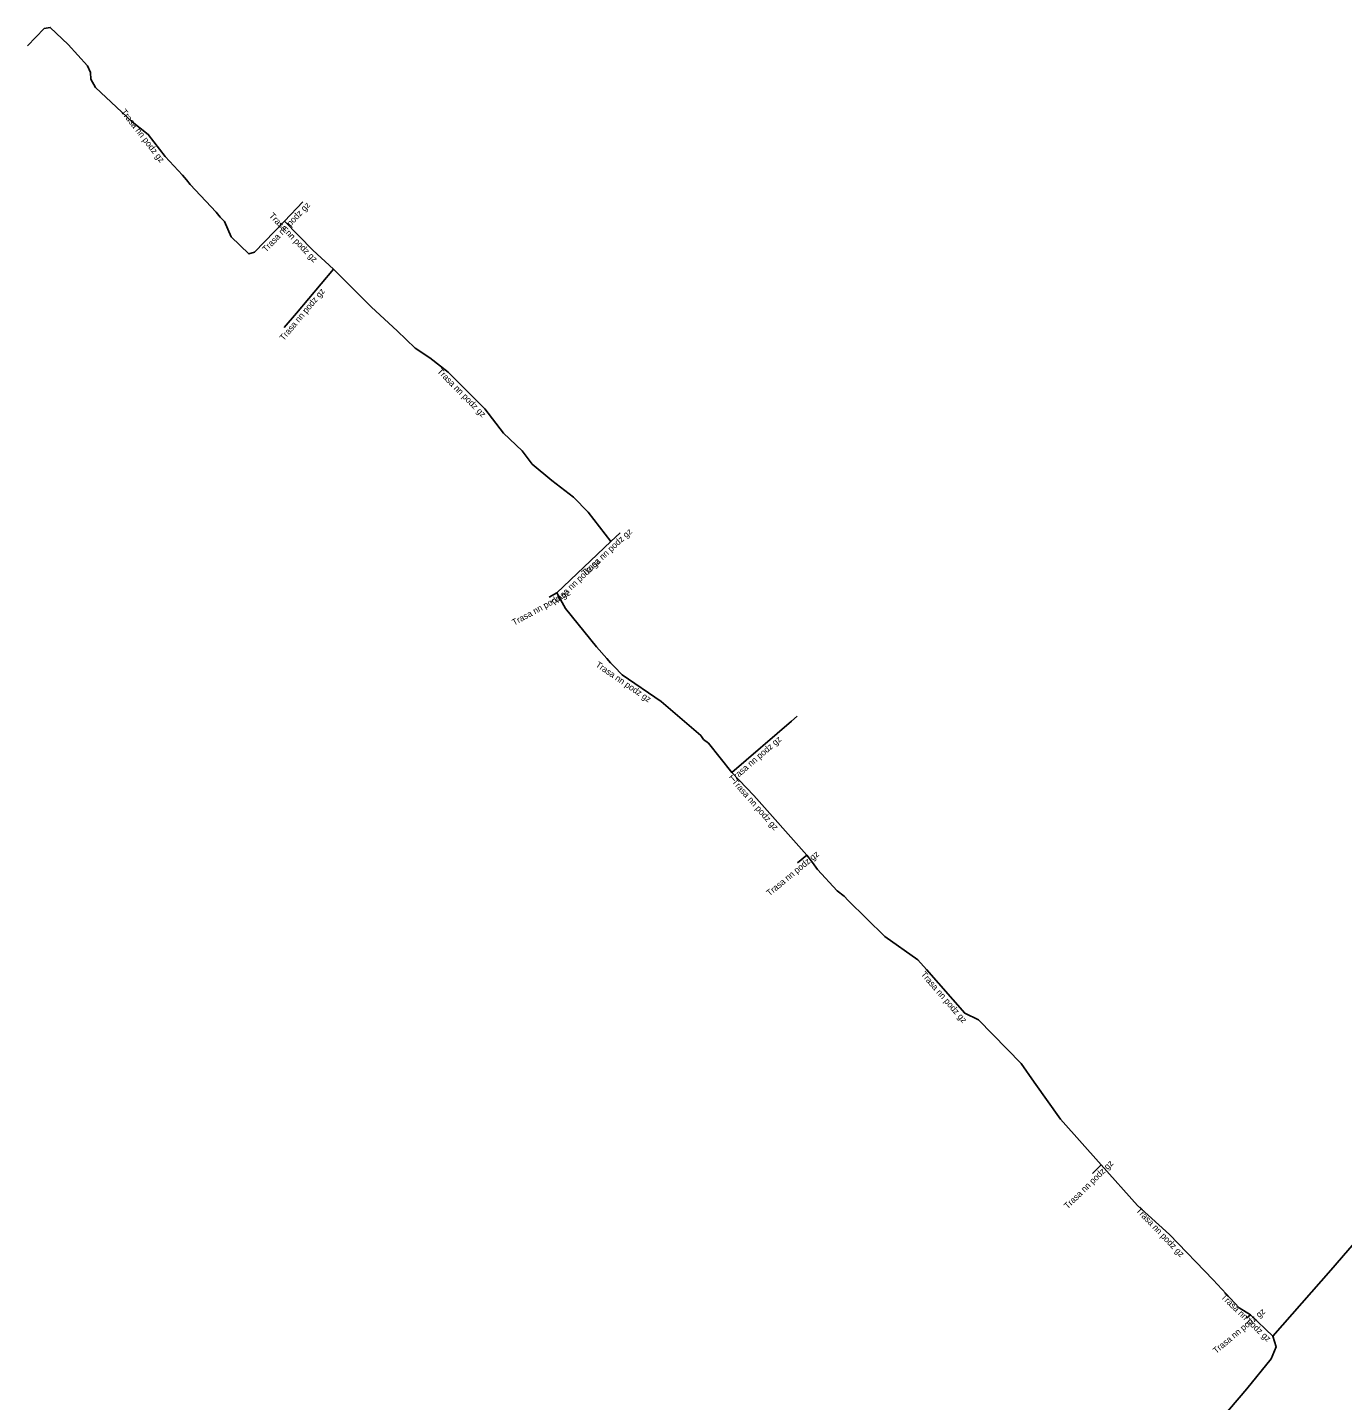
# Model space of a CAD drawing. Extents: x -747130 to -746834, y -1018555 to -1017941.
# Drawn here: x -747129.6 to -747024.9, y -1018393 to -1018283.6 of the extents above; entities that cross this region are included whole.
import ezdxf

# ---------------------------------------------------------------- set-up
doc = ezdxf.new("R2010")
doc.units = 0
doc.layers.add('Popiskový text - Ostatní atributy Trasy', color=7, linetype='Continuous')
doc.layers.add('Spojnice NN', color=7, linetype='Continuous')

msp = doc.modelspace()

# ---------------------------------------------------------------- linework, layer by layer
at = {"layer": 'Spojnice NN'}
for points in [[(-747129.62, -1018285.07), (-747128.29, -1018283.69), (-747127.81, -1018283.61), (-747126.37, -1018284.96), (-747124.84, -1018286.67), (-747124.61, -1018287.19), (-747124.57, -1018287.73), (-747124.21, -1018288.38), (-747121.28, -1018291.12), (-747120.01, -1018292.13), (-747118.65, -1018293.88), (-747117.29, -1018295.38), (-747116.96, -1018295.74), (-747116.67, -1018296.13), (-747114.61, -1018298.32), (-747114.28, -1018298.72), (-747113.95, -1018299.06), (-747113.41, -1018300.29), (-747112, -1018301.65), (-747111.54, -1018301.5), (-747109.15, -1018299.04)], [(-747109.15, -1018299.04), (-747107.7, -1018297.5)], [(-747109.15, -1018299.04), (-747106.9, -1018301.36), (-747105.27, -1018302.85)], [(-747109.2, -1018307.51), (-747108.2, -1018306.36), (-747105.27, -1018302.85)], [(-747105.27, -1018302.85), (-747102.24, -1018305.9), (-747100.19, -1018307.78), (-747098.77, -1018309.16), (-747097.6, -1018309.91), (-747096.12, -1018311.06), (-747093.22, -1018313.99), (-747091.74, -1018315.92), (-747090.23, -1018317.33), (-747089.45, -1018318.39), (-747087.87, -1018319.7), (-747086.15, -1018321.03), (-747085, -1018322.22), (-747083.18, -1018324.55)], [(-747083.18, -1018324.55), (-747082.45, -1018323.87)], [(-747087.47, -1018328.65), (-747083.18, -1018324.55)], [(-747087.47, -1018328.65), (-747088.09, -1018328.99)], [(-747087.47, -1018328.65), (-747086.8, -1018329.9), (-747084.32, -1018332.95), (-747083.5, -1018333.86), (-747083.21, -1018334.21), (-747082.91, -1018334.52), (-747082.29, -1018335.17), (-747079.18, -1018337.29), (-747076.03, -1018339.99), (-747075.8, -1018340.32), (-747075.42, -1018340.6), (-747073.54, -1018342.96)], [(-747068.36, -1018338.46), (-747068.8, -1018338.87), (-747073.54, -1018342.96)], [(-747073.54, -1018342.96), (-747071.79, -1018344.77), (-747067.59, -1018349.54)], [(-747067.59, -1018349.54), (-747068.33, -1018350.15)], [(-747067.59, -1018349.54), (-747067.12, -1018350.11), (-747066.73, -1018350.68), (-747065.16, -1018352.38), (-747064.61, -1018352.8), (-747064.28, -1018353.15), (-747061.37, -1018356), (-747058.76, -1018357.87), (-747058.05, -1018358.63), (-747055.01, -1018362.13), (-747053.92, -1018362.65), (-747050.53, -1018366.13), (-747049.5, -1018367.62), (-747047.4, -1018370.55), (-747044.15, -1018374.21)], [(-747030.49, -1018387.84), (-747025.86, -1018382.59), (-747018.77, -1018374.36), (-747011.83, -1018366.33), (-747006.47, -1018360.35), (-747002.76, -1018356.27), (-747001.95, -1018355.16), (-747001.69, -1018354.42), (-747001.81, -1018353.62)], [(-747044.15, -1018374.21), (-747044.85, -1018374.9)], [(-747032.28, -1018386.14), (-747033.18, -1018385.58), (-747035.23, -1018383.36), (-747038.72, -1018379.74), (-747041.25, -1018377.44), (-747044.15, -1018374.21)], [(-747032.28, -1018386.14), (-747032.59, -1018386.4)], [(-747030.49, -1018387.84), (-747032.28, -1018386.14)], [(-747037.93, -1018398.33), (-747032.55, -1018392.05), (-747030.63, -1018389.65), (-747030.23, -1018388.68), (-747030.49, -1018387.84)]]:
    msp.add_lwpolyline(points, dxfattribs=at)

# ---------------------------------------------------------------- texts
at = {"layer": 'Popiskový text - Ostatní atributy Trasy'}
for rotation, p in [(307.8523, (-747122.22, -1018290.35)), (46.7241, (-747110.62, -1018301.55)), (314.1225, (-747110.43, -1018298.65)), (50.1463, (-747109.22, -1018308.6)), (314.7052, (-747097.05, -1018311.04)), (42.9691, (-747085.22, -1018327.34)), (43.7027, (-747087.69, -1018329.76)), (28.7398, (-747090.88, -1018331.26)), (325.7188, (-747084.45, -1018334.48)), (40.7899, (-747073.47, -1018343.75)), (311.364, (-747073.58, -1018343.72)), (39.4996, (-747070.55, -1018352.82)), (310.9766, (-747058.55, -1018359.05)), (44.5878, (-747046.82, -1018377.75)), (313.9525, (-747041.42, -1018377.87)), (316.4772, (-747034.66, -1018384.78)), (39.9869, (-747035, -1018389.27))]:
    msp.add_text('Trasa nn podz gz', height=0.5, rotation=rotation, dxfattribs=at).set_placement(p)

doc.saveas('drawing.dxf')
